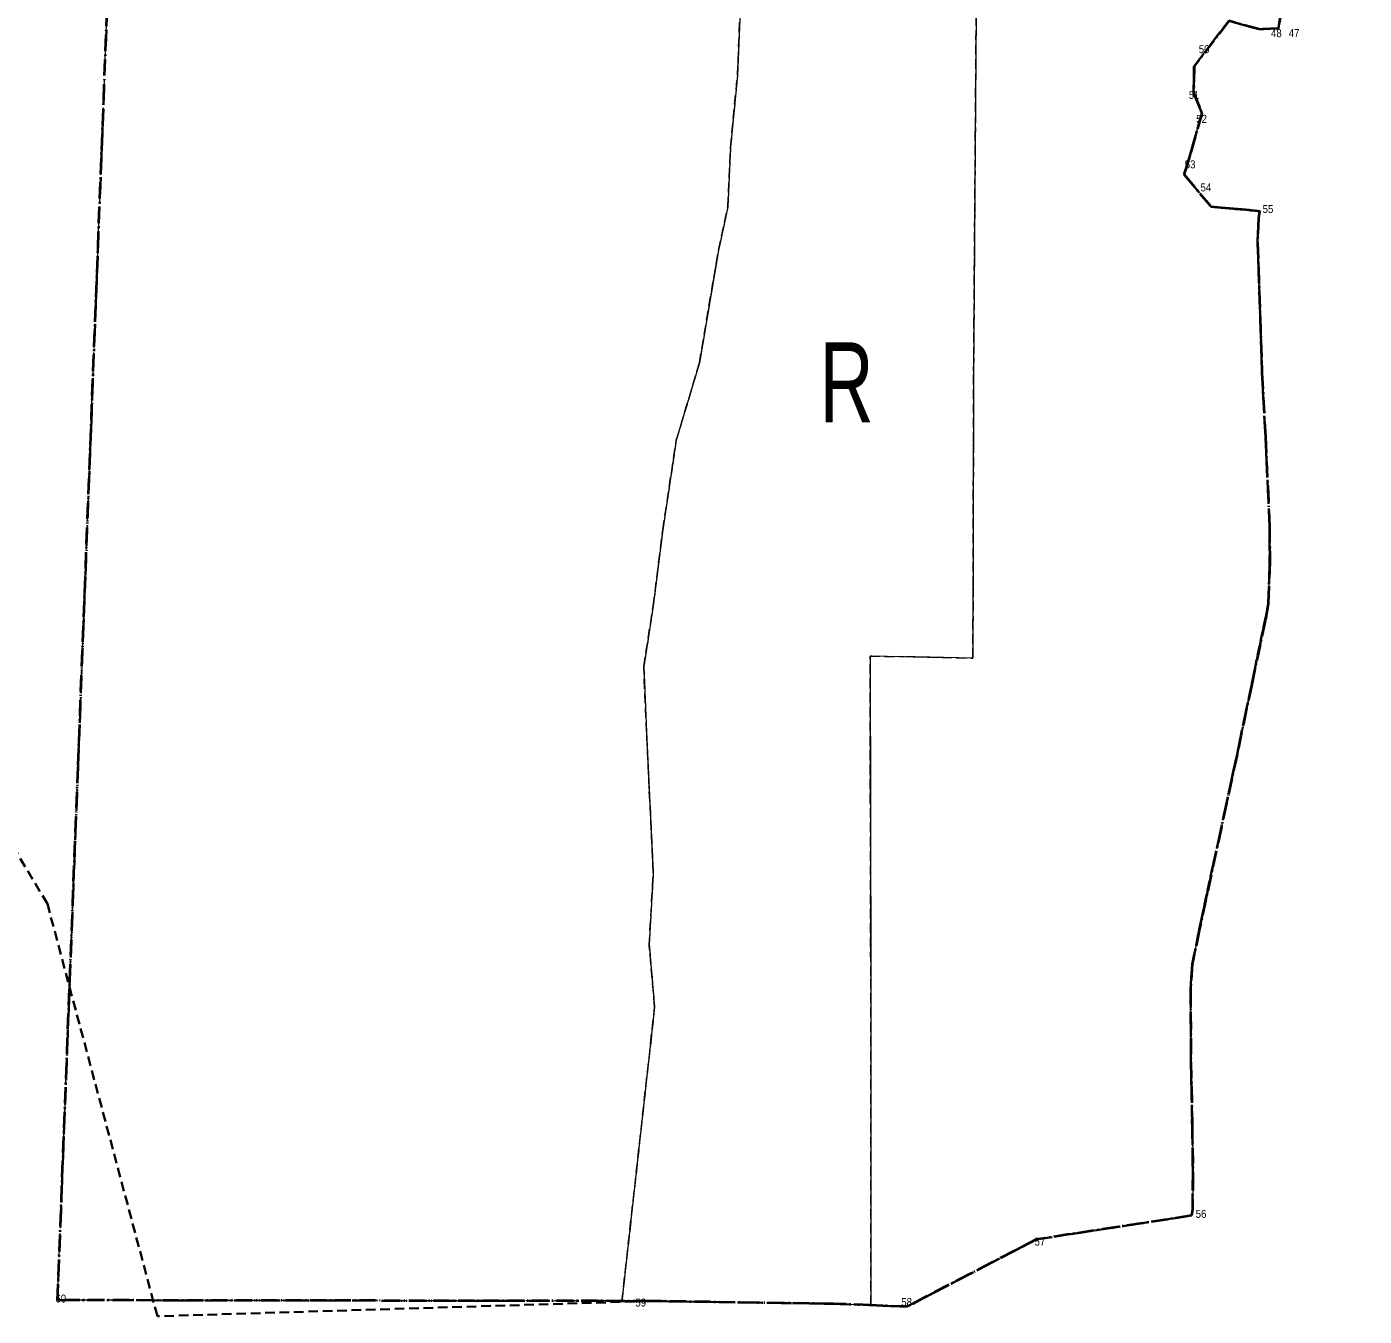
# Model space of a CAD drawing. Extents: x 338337 to 345629, y 338092 to 349945.
# Drawn here: x 341668 to 345011, y 338092 to 341315 of the extents above; entities that cross this region are included whole.
import ezdxf

# ---------------------------------------------------------------- set-up
doc = ezdxf.new("R2010")
doc.units = 0
doc.header["$LTSCALE"] = 8
for name, pattern in [('DASH_DOUBLE_DOT', [9.2, 5, -1.2, 0.3, -1.2, 0.3, -1.2]), ('DOT_DASHED', [7.7, 5, -1.2, 0.3, -1.2]), ('MEDIUM_DASHED', [4.5, 3, -1.5])]:
    doc.linetypes.add(name, pattern=pattern)
for name, color, linetype, lineweight in [('26', 7, 'DASH_DOUBLE_DOT', 35), ('28', 7, 'Continuous', 13), ('30', 7, 'DOT_DASHED', 40), ('31', 7, 'MEDIUM_DASHED', 13), ('32', 7, 'MEDIUM_DASHED', 13), ('35', 7, 'MEDIUM_DASHED', 35)]:
    doc.layers.add(name, color=color, linetype=linetype, lineweight=lineweight)
doc.layers.add('29', color=7, linetype='Continuous')
doc.layers.add('36', color=7, linetype='Continuous')

msp = doc.modelspace()

# ---------------------------------------------------------------- linework, layer by layer
at = {"layer": '26'}
for points in [[(343976.39, 349474.549), (342197.475, 349919.528), (342109.457, 347629.74), (342004.932, 344909.777), (341900.436, 342189.822), (341795.969, 339469.876), (341744.602, 338132.109), (343155.288, 338130.097)], [(343777.034, 338119.48), (343868, 338116), (344191, 338284), (344578.717, 338343.46), (344581.379, 338358.446), (344582.279, 338446.198), (344580.342, 338575.635), (344577.619, 338728.234), (344576.104, 338910.329), (344580.861, 338971.809), (344598.14, 339057.33), (344692.696, 339496.138), (344729.372, 339672.3), (344763.084, 339831.218), (344770.663, 339872.797), (344774.494, 339977.005), (344774.11, 340065.804), (344763.566, 340290.508), (344755.119, 340450.521), (344744.202, 340776.35), (344746.587, 340837.622), (344748.984, 340853.001), (344750.587, 340854.138), (344723.363, 340857.37), (344653.101, 340863.326), (344627.374, 340866.423), (344560.481, 340945.906), (344574.889, 340993.39), (344604.559, 341099.313), (344584.217, 341151.3), (344585.47, 341216.478), (344672.004, 341329.751), (344748.271, 341309.232), (344795.984, 341310.949), (344824.663, 341485.966)], [(343155.288, 338130.097), (343223, 338130), (343685, 338123), (343777.034, 338119.48)]]:
    msp.add_lwpolyline(points, dxfattribs=at)
at = {"layer": '28'}
for points in [[(344441.327, 345112.197), (344457.063, 344119.784), (344053.154, 344062.574), (344050.305, 343853.171), (344049.994, 343822.032), (344051.541, 343412.126), (344044.847, 342988.406), (344044.846, 342671.198), (344046.608, 342221.819), (344044.846, 341927.52), (344034.278, 340454.262), (344032.516, 339737.018), (343775.322, 339742.305), (343777.084, 338942.234), (343777.034, 338119.48)], [(343450.615, 341353.173), (343443.831, 341193.811), (343426.87, 341014.103), (343420.086, 340864.911), (343396.341, 340756.409), (343348.852, 340474.979), (343291.187, 340281.707), (343257.266, 340057.921), (343233.521, 339868.041), (343209.776, 339715.457), (343216.561, 339552.703), (343223.345, 339410.293), (343233.521, 339200.069), (343223.344, 339020.361), (343236.913, 338864.389), (343155.288, 338130.097)]]:
    msp.add_lwpolyline(points, dxfattribs=at)
at = {"layer": '30'}
for points in [[(343155.288, 338130.097), (341744.602, 338132.109), (341795.969, 339469.876), (341900.436, 342189.822), (342004.932, 344909.777), (342109.457, 347629.74)], [(344824.663, 341485.966), (344795.984, 341310.949), (344748.271, 341309.232), (344672.004, 341329.751), (344585.47, 341216.478), (344584.217, 341151.3), (344604.559, 341099.313), (344574.889, 340993.39), (344560.481, 340945.906), (344627.374, 340866.423), (344653.101, 340863.326), (344723.363, 340857.37), (344750.587, 340854.138), (344748.984, 340853.001), (344746.587, 340837.622), (344744.202, 340776.35), (344755.119, 340450.521), (344763.566, 340290.508), (344774.11, 340065.804), (344774.494, 339977.005), (344770.663, 339872.797), (344763.084, 339831.218), (344729.372, 339672.3), (344692.696, 339496.138), (344598.14, 339057.33), (344580.861, 338971.809), (344576.104, 338910.329), (344577.619, 338728.234), (344580.342, 338575.635), (344582.279, 338446.198), (344581.379, 338358.446), (344578.717, 338343.46), (344191, 338284), (343868, 338116), (343777.034, 338119.48), (343685, 338123), (343223, 338130), (343155.288, 338130.097)]]:
    msp.add_lwpolyline(points, dxfattribs=at)
at = {"layer": '31'}
msp.add_lwpolyline([(344044.846, 341927.52), (344034.278, 340454.262), (344032.516, 339737.018), (343775.322, 339742.305), (343777.084, 338942.234), (343777.034, 338119.48), (343685, 338123), (343223, 338130), (343155.288, 338130.097), (343236.913, 338864.389), (343223.344, 339020.361), (343233.521, 339200.069), (343223.345, 339410.293), (343216.561, 339552.703), (343209.776, 339715.457), (343233.521, 339868.041), (343257.266, 340057.921), (343291.187, 340281.707), (343348.852, 340474.979), (343396.341, 340756.409), (343420.086, 340864.911), (343426.87, 341014.103), (343443.831, 341193.811), (343450.615, 341353.173)], dxfattribs=at)
at = {"layer": '32'}
for points in [[(343450.615, 341353.173), (343443.831, 341193.811), (343426.87, 341014.103), (343420.086, 340864.911), (343396.341, 340756.409), (343348.852, 340474.979), (343291.187, 340281.707), (343257.266, 340057.921), (343233.521, 339868.041), (343209.776, 339715.457), (343216.561, 339552.703), (343223.345, 339410.293), (343233.521, 339200.069), (343223.344, 339020.361), (343236.913, 338864.389), (343155.288, 338130.097), (341744.602, 338132.109), (341795.969, 339469.876), (341900.436, 342189.822)], [(343777.034, 338119.48), (343777.084, 338942.234), (343775.322, 339742.305), (344032.516, 339737.018), (344034.278, 340454.262), (344044.846, 341927.52)], [(344824.663, 341485.966), (344795.984, 341310.949), (344748.271, 341309.232), (344672.004, 341329.751), (344585.47, 341216.478), (344584.217, 341151.3), (344604.559, 341099.313), (344574.889, 340993.39), (344560.481, 340945.906), (344627.374, 340866.423), (344653.101, 340863.326), (344723.363, 340857.37), (344750.587, 340854.138), (344748.984, 340853.001), (344746.587, 340837.622), (344744.202, 340776.35), (344755.119, 340450.521), (344763.566, 340290.508), (344774.11, 340065.804), (344774.494, 339977.005), (344770.663, 339872.797), (344763.084, 339831.218), (344729.372, 339672.3), (344692.696, 339496.138), (344598.14, 339057.33), (344580.861, 338971.809), (344576.104, 338910.329), (344577.619, 338728.234), (344580.342, 338575.635), (344582.279, 338446.198), (344581.379, 338358.446), (344578.717, 338343.46), (344191, 338284), (343868, 338116), (343777.034, 338119.48)]]:
    msp.add_lwpolyline(points, dxfattribs=at)
at = {"layer": '35'}
for points in [[(345010.736, 341736.76), (344981.036, 341681.095), (344922, 341638), (344861, 341601), (344816, 341539), (344825, 341486), (344796, 341311), (344748, 341309), (344672, 341330), (344585, 341216), (344585, 341170), (344584, 341151), (344605, 341099), (344600, 341083), (344575, 340993), (344560, 340946), (344627, 340866), (344653, 340863), (344751, 340854)], [(344751, 340854), (344748.984, 340853.001), (344746.587, 340837.622), (344744, 340776), (344748, 340669)], [(344748, 340669), (344755.119, 340450.521), (344763.566, 340290.508), (344774, 340066), (344774, 339953), (344771, 339873)], [(344580.861, 338971.809), (344577, 338924), (344577.619, 338728.234), (344582, 338467), (344581.379, 338358.446), (344578.717, 338343.46), (344191, 338284), (343868, 338116), (343685, 338123), (343223, 338130), (341994, 338092), (341719, 339123), (341199, 339996)], [(344771, 339873), (344692.696, 339496.138), (344603, 339082), (344580.861, 338971.809)]]:
    msp.add_lwpolyline(points, dxfattribs=at)

# ---------------------------------------------------------------- texts
at = {"layer": '29', "width": 0.7}
msp.add_text('R', height=200, dxfattribs=at).set_placement((343649.326, 340326.478))
at = {"layer": '36'}
for s, width, p in [('48', 0.9, (344777.652, 341289.352)), ('47', 0.9, (344821.953, 341289.352)), ('50', 0.9, (344597.081, 341249.252)), ('51', 0.85, (344572.588, 341134.904)), ('52', 0.9, (344590.602, 341075.104)), ('53', 0.9, (344562.047, 340961.289)), ('54', 0.9, (344601.47, 340903.744)), ('55', 0.9, (344756.732, 340849.774)), ('56', 0.9, (344589.373, 338337.897)), ('57', 0.9, (344186.598, 338268.824)), ('60', 0.9, (341739.216, 338126.284)), ('59', 0.9, (343188.961, 338116.262)), ('58', 0.9, (343853.479, 338117.493))]:
    msp.add_text(s, height=20, dxfattribs=dict(at, width=width)).set_placement(p)

doc.saveas('drawing.dxf')
